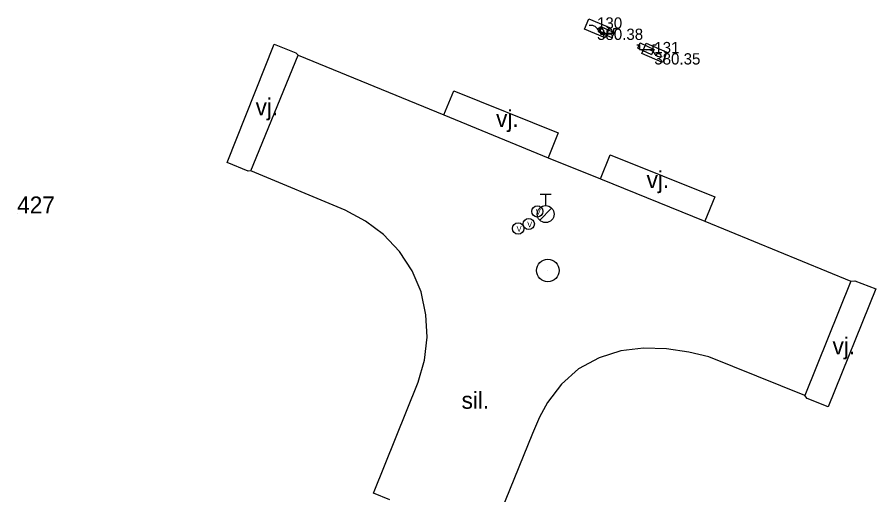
# Model space of a CAD drawing. Extents: x -836568 to -836015, y -1070547 to -1070212.
# Drawn here: x -836354.52 to -836316.42, y -1070383.27 to -1070362.09 of the extents above; entities that cross this region are included whole.
import ezdxf

# ---------------------------------------------------------------- set-up
doc = ezdxf.new("R2010")
doc.units = 0
for name, color, linetype in [('BodPole_mer', 7, 'Continuous'), ('BodPole_popis', 7, 'Continuous'), ('Doprava_hranice', 7, 'Continuous'), ('Doprava_kody', 7, 'Continuous'), ('PovrZnIS_body', 7, 'Continuous'), ('PovrZnIS_hranice', 7, 'Continuous'), ('PovrZnIS_kody', 7, 'Continuous'), ('RuianPar_popis', 7, 'Continuous')]:
    doc.layers.add(name, color=color, linetype=linetype)

msp = doc.modelspace()

# ---------------------------------------------------------------- linework, layer by layer
at = {"layer": 'BodPole_mer'}
for p, q in [((-836328.79, -1070362.6), (-836328.79, -1070362.6)), ((-836328.63, -1070362.51), (-836328.63, -1070362.51)), ((-836328.63, -1070362.51), (-836328.63, -1070362.51)), ((-836328.73, -1070362.74), (-836328.73, -1070362.74)), ((-836328.73, -1070362.74), (-836328.73, -1070362.74)), ((-836328.13, -1070363), (-836328.13, -1070363)), ((-836328.13, -1070363), (-836328.13, -1070363)), ((-836328.03, -1070362.77), (-836328.03, -1070362.77)), ((-836328.03, -1070362.77), (-836328.03, -1070362.77)), ((-836343.11, -1070363.29), (-836343.11, -1070363.29)), ((-836326.98, -1070363.46), (-836326.98, -1070363.46)), ((-836326.98, -1070363.46), (-836326.98, -1070363.46)), ((-836326.87, -1070363.23), (-836326.87, -1070363.23)), ((-836326.87, -1070363.23), (-836326.87, -1070363.23)), ((-836342.16, -1070363.67), (-836342.16, -1070363.67)), ((-836342.05, -1070363.78), (-836342.05, -1070363.78)), ((-836326.37, -1070363.75), (-836326.37, -1070363.75)), ((-836326.37, -1070363.75), (-836326.37, -1070363.75)), ((-836326.26, -1070363.52), (-836326.26, -1070363.52)), ((-836326.26, -1070363.52), (-836326.26, -1070363.52)), ((-836326.25, -1070363.69), (-836326.25, -1070363.69)), ((-836335.15, -1070365.35), (-836335.15, -1070365.35)), ((-836335.59, -1070366.42), (-836335.59, -1070366.42)), ((-836330.52, -1070367.22), (-836330.52, -1070367.22)), ((-836330.96, -1070368.32), (-836330.96, -1070368.32)), ((-836328.21, -1070368.2), (-836328.21, -1070368.2)), ((-836345.2, -1070368.53), (-836345.2, -1070368.53)), ((-836344.27, -1070368.92), (-836344.27, -1070368.92)), ((-836344.15, -1070368.91), (-836344.15, -1070368.91)), ((-836328.64, -1070369.26), (-836328.64, -1070369.26)), ((-836323.57, -1070370.06), (-836323.57, -1070370.06)), ((-836339.97, -1070370.65), (-836339.97, -1070370.65)), ((-836331.44, -1070370.7), (-836331.44, -1070370.7)), ((-836331.07, -1070370.82), (-836331.07, -1070370.82)), ((-836339.07, -1070371.13), (-836339.07, -1070371.13)), ((-836332.29, -1070371.46), (-836332.29, -1070371.46)), ((-836331.82, -1070371.26), (-836331.82, -1070371.26)), ((-836324, -1070371.14), (-836324, -1070371.14)), ((-836338.26, -1070371.73), (-836338.26, -1070371.73)), ((-836337.55, -1070372.48), (-836337.55, -1070372.48)), ((-836336.99, -1070373.33), (-836336.99, -1070373.33)), ((-836330.97, -1070373.32), (-836330.97, -1070373.32)), ((-836317.53, -1070373.79), (-836317.53, -1070373.79)), ((-836317.35, -1070373.78), (-836317.35, -1070373.78)), ((-836316.42, -1070374.14), (-836316.42, -1070374.14)), ((-836336.6, -1070374.27), (-836336.6, -1070374.27)), ((-836336.39, -1070375.29), (-836336.39, -1070375.29)), ((-836336.33, -1070376.28), (-836336.33, -1070376.28)), ((-836326.73, -1070376.77), (-836326.73, -1070376.77)), ((-836325.71, -1070376.8), (-836325.71, -1070376.8)), ((-836328.7, -1070377.19), (-836328.7, -1070377.19)), ((-836327.73, -1070376.89), (-836327.73, -1070376.89)), ((-836324.72, -1070376.94), (-836324.72, -1070376.94)), ((-836323.83, -1070377.15), (-836323.83, -1070377.15)), ((-836336.45, -1070377.29), (-836336.45, -1070377.29)), ((-836329.61, -1070377.68), (-836329.61, -1070377.68)), ((-836336.73, -1070378.27), (-836336.73, -1070378.27)), ((-836330.37, -1070378.36), (-836330.37, -1070378.36)), ((-836319.57, -1070378.86), (-836319.57, -1070378.86)), ((-836319.46, -1070378.99), (-836319.46, -1070378.99)), ((-836330.99, -1070379.17), (-836330.99, -1070379.17)), ((-836318.53, -1070379.36), (-836318.53, -1070379.36)), ((-836331.34, -1070379.82), (-836331.34, -1070379.82)), ((-836331.66, -1070380.54), (-836331.66, -1070380.54)), ((-836338.71, -1070383.19), (-836338.71, -1070383.19))]:
    msp.add_line(p, q, dxfattribs=at)
at = {"layer": 'Doprava_hranice'}
for points in [[(-836344.15, -1070368.91), (-836344.27, -1070368.92), (-836345.2, -1070368.53), (-836343.11, -1070363.29), (-836342.16, -1070363.67), (-836342.05, -1070363.78)], [(-836336.73, -1070378.27), (-836336.45, -1070377.29), (-836336.33, -1070376.28), (-836336.39, -1070375.29), (-836336.6, -1070374.27), (-836336.99, -1070373.33), (-836337.55, -1070372.48), (-836338.26, -1070371.73), (-836339.07, -1070371.13), (-836339.97, -1070370.65), (-836344.15, -1070368.91), (-836342.05, -1070363.78), (-836335.59, -1070366.42), (-836330.96, -1070368.32), (-836328.64, -1070369.26), (-836324, -1070371.14), (-836317.53, -1070373.79), (-836319.57, -1070378.86), (-836323.83, -1070377.15), (-836324.72, -1070376.94), (-836325.71, -1070376.8), (-836326.73, -1070376.77), (-836327.73, -1070376.89), (-836328.7, -1070377.19), (-836329.61, -1070377.68), (-836330.37, -1070378.36), (-836330.99, -1070379.17), (-836331.34, -1070379.82), (-836331.66, -1070380.54), (-836339.56, -1070400.02)], [(-836335.59, -1070366.42), (-836335.15, -1070365.35), (-836330.52, -1070367.22), (-836330.96, -1070368.32)], [(-836328.64, -1070369.26), (-836328.21, -1070368.2), (-836323.57, -1070370.06), (-836324, -1070371.14)], [(-836317.53, -1070373.79), (-836317.35, -1070373.78), (-836316.42, -1070374.14), (-836318.53, -1070379.36), (-836319.46, -1070378.99), (-836319.57, -1070378.86)], [(-836337.99, -1070383.49), (-836338.71, -1070383.19), (-836336.73, -1070378.27)]]:
    msp.add_lwpolyline(points, dxfattribs=at)
at = {"layer": 'PovrZnIS_body'}
for p, q in [((-836329.348, -1070362.621), (-836329.152, -1070362.161)), ((-836329.152, -1070362.161), (-836328.232, -1070362.553)), ((-836328.428, -1070363.013), (-836329.348, -1070362.621)), ((-836328.232, -1070362.553), (-836328.428, -1070363.013)), ((-836326.808, -1070363.704), (-836326.606, -1070363.247)), ((-836326.606, -1070363.247), (-836325.691, -1070363.65)), ((-836325.893, -1070364.108), (-836326.808, -1070363.704)), ((-836325.691, -1070363.65), (-836325.893, -1070364.108)), ((-836331.32, -1070369.945), (-836330.82, -1070369.945)), ((-836331.07, -1070369.945), (-836331.07, -1070370.445)), ((-836330.805, -1070370.555), (-836331.335, -1070371.085))]:
    msp.add_line(p, q, dxfattribs=at)
for points in [[(-836329.136, -1070362.452), (-836329.089, -1070362.445), (-836329.039, -1070362.444), (-836328.988, -1070362.452), (-836328.939, -1070362.469), (-836328.893, -1070362.493), (-836328.852, -1070362.524), (-836328.817, -1070362.56), (-836328.79, -1070362.6)], [(-836328.79, -1070362.6), (-836328.763, -1070362.64), (-836328.729, -1070362.676), (-836328.688, -1070362.707), (-836328.642, -1070362.731), (-836328.593, -1070362.747), (-836328.542, -1070362.755), (-836328.492, -1070362.755), (-836328.445, -1070362.747)], [(-836326.595, -1070363.538), (-836326.547, -1070363.531), (-836326.497, -1070363.531), (-836326.446, -1070363.54), (-836326.397, -1070363.557), (-836326.351, -1070363.582), (-836326.311, -1070363.613), (-836326.277, -1070363.65), (-836326.25, -1070363.69)], [(-836326.25, -1070363.69), (-836326.223, -1070363.73), (-836326.19, -1070363.766), (-836326.149, -1070363.798), (-836326.104, -1070363.823), (-836326.055, -1070363.84), (-836326.004, -1070363.848), (-836325.954, -1070363.848), (-836325.907, -1070363.841)]]:
    msp.add_lwpolyline(points, dxfattribs=at)
for centre, radius in [((-836331.44, -1070370.7), 0.25), ((-836331.07, -1070370.82), 0.375), ((-836331.82, -1070371.26), 0.25), ((-836332.29, -1070371.46), 0.25), ((-836330.97, -1070373.32), 0.5)]:
    msp.add_circle(centre, radius, dxfattribs=at)
at = {"layer": 'PovrZnIS_hranice'}
for p, q in [((-836328.73, -1070362.74), (-836328.13, -1070363)), ((-836328.73, -1070362.74), (-836328.13, -1070363)), ((-836326.98, -1070363.46), (-836326.37, -1070363.75)), ((-836326.98, -1070363.46), (-836326.37, -1070363.75))]:
    msp.add_line(p, q, dxfattribs=at)
for points in [[(-836328.73, -1070362.74), (-836328.63, -1070362.51), (-836328.03, -1070362.77), (-836328.13, -1070363)], [(-836328.73, -1070362.74), (-836328.63, -1070362.51), (-836328.03, -1070362.77), (-836328.13, -1070363)], [(-836326.98, -1070363.46), (-836326.87, -1070363.23), (-836326.26, -1070363.52), (-836326.37, -1070363.75)], [(-836326.98, -1070363.46), (-836326.87, -1070363.23), (-836326.26, -1070363.52), (-836326.37, -1070363.75)]]:
    msp.add_lwpolyline(points, dxfattribs=at)
at = {"layer": 'PovrZnIS_kody'}
for p, q in [((-836328.771, -1070362.6), (-836328.65, -1070362.6)), ((-836328.771, -1070362.6), (-836328.65, -1070362.6)), ((-836328.65, -1070362.6), (-836328.65, -1070362.8)), ((-836328.65, -1070362.6), (-836328.65, -1070362.8)), ((-836328.05, -1070362.8), (-836328.05, -1070362.6)), ((-836328.05, -1070362.6), (-836327.916, -1070362.6)), ((-836328.05, -1070362.8), (-836328.05, -1070362.6)), ((-836328.05, -1070362.6), (-836327.916, -1070362.6)), ((-836328.65, -1070362.8), (-836328.05, -1070362.8)), ((-836328.65, -1070362.8), (-836328.05, -1070362.8)), ((-836327.021, -1070363.32), (-836326.9, -1070363.32)), ((-836327.021, -1070363.32), (-836326.9, -1070363.32)), ((-836326.9, -1070363.32), (-836326.9, -1070363.52)), ((-836326.9, -1070363.32), (-836326.9, -1070363.52)), ((-836326.3, -1070363.52), (-836326.3, -1070363.32)), ((-836326.3, -1070363.32), (-836326.166, -1070363.32)), ((-836326.3, -1070363.52), (-836326.3, -1070363.32)), ((-836326.3, -1070363.32), (-836326.166, -1070363.32)), ((-836326.9, -1070363.52), (-836326.3, -1070363.52)), ((-836326.9, -1070363.52), (-836326.3, -1070363.52))]:
    msp.add_line(p, q, dxfattribs=at)
at = {"layer": 'RuianPar_popis'}
msp.add_line((-836354.52, -1070370.79), (-836354.52, -1070370.79), dxfattribs=at)

# ---------------------------------------------------------------- texts
at = {"layer": 'BodPole_popis'}
for s, p in [('130', (-836328.79, -1070362.6)), ('380.38', (-836328.79, -1070363.1)), ('131', (-836326.25, -1070363.69)), ('380.35', (-836326.25, -1070364.19))]:
    msp.add_text(s, height=0.5, dxfattribs=at).set_placement(p)
at = {"layer": 'Doprava_kody'}
for s, p in [('vj.', (-836343.94, -1070366.44)), ('vj.', (-836333.27, -1070366.96)), ('vj.', (-836326.59, -1070369.67)), ('vj.', (-836318.34, -1070377.04)), ('sil.', (-836334.8, -1070379.45))]:
    msp.add_text(s, height=0.75, dxfattribs=at).set_placement(p)
at = {"layer": 'PovrZnIS_body'}
for p in [(-836331.511, -1070370.843), (-836332.361, -1070371.603), (-836331.891, -1070371.403)]:
    msp.add_text('V', height=0.25, dxfattribs=at).set_placement(p)
at = {"layer": 'RuianPar_popis'}
msp.add_text('427', height=0.75, dxfattribs=at).set_placement((-836354.52, -1070370.79))

doc.saveas('drawing.dxf')
